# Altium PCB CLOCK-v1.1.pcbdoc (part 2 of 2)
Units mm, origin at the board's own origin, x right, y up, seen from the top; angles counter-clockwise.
Board outline 180 x 92.5 mm, 2 copper layers (Top Layer, Bottom Layer); 120 components, 111 nets, 414 pads, 6 vias.
Unrouted connection lines stored in the file: 2.
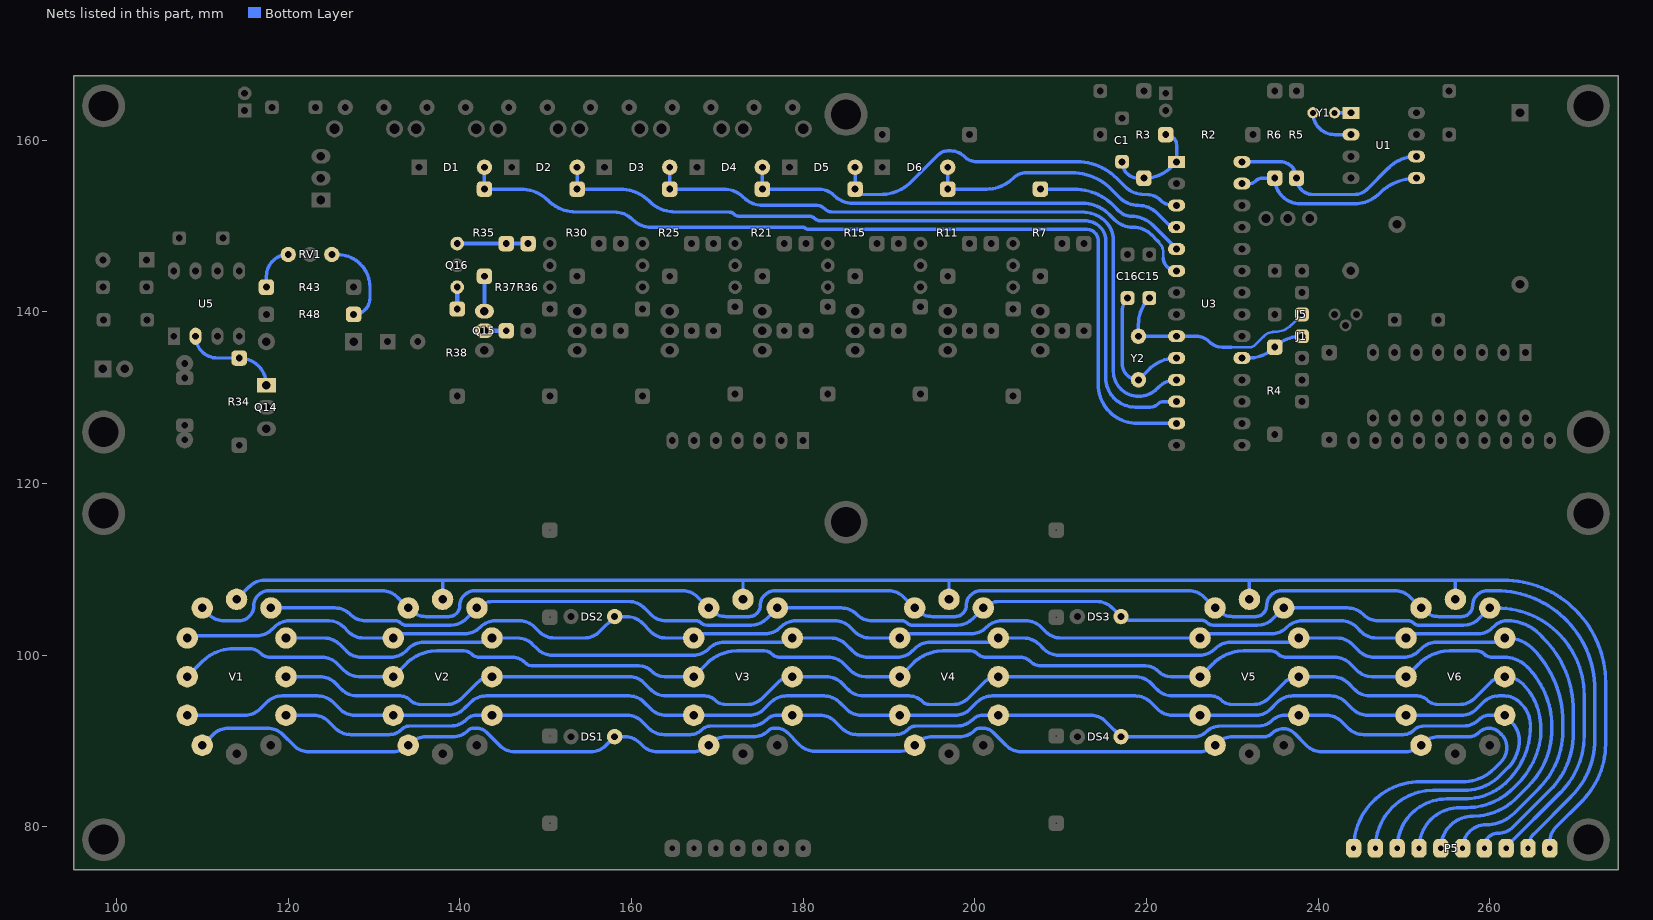
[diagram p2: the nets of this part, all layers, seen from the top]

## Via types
v1: diameter 1.6, hole 0.8, Top Layer to Bottom Layer, 6 vias

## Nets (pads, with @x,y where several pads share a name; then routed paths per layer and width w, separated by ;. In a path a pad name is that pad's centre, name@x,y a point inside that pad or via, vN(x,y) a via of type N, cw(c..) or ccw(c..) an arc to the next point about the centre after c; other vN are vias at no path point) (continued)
NetQ14_1: Q14.1 R34.2 U5.2 | length 15.5
  Bottom Layer w0.4: Q14.1@117.475,131.445 ccw(c114.3,131.445) R34.2@114.3,134.62 111.76,134.62 ; 111.76,134.62 cw(c111.76,137.16) U5.2@109.22,137.16 ccw(c111.76,137.16) 111.76,134.62
NetQ15_2: Q15.2 R37.1 | length 2.5
  Bottom Layer w0.5: Q15.2@142.875,137.795 R37.1@145.415,137.795
NetQ15_3: Q15.3 R35.2 | length 4.1
  Bottom Layer w0.5: Q15.3@142.875,140.081 R35.2@142.875,144.145
NetQ16_1: Q16.1 R38.2 | length 2.5
  Bottom Layer w0.5: R38.2@139.7,140.335 Q16.1@139.7,142.875
NetQ16_3: Q16.3 R36.1 R37.2 | length 8.3
  Bottom Layer w0.5: Q16.3@139.7,147.955 R37.2@145.415,147.955 R36.1@147.955,147.955
NetR43_1: R43.1 RV1.1 | length 5.3
  Bottom Layer w0.4: R43.1@117.475,142.875 117.475,144.145 cw(c120.015,144.145) RV1.1@120.015,146.685
NetR48_1: R48.1 RV1.3 | length 10.9
  Bottom Layer w0.4: RV1.3@125.095,146.685 125.73,146.685 cw(c125.73,142.875) 129.54,142.875 129.54,141.605 cw(c127.635,141.605) R48.1@127.635,139.7
NetU1_1: U1.1 Y1.1 | length 1.9
  Bottom Layer w0.4: Y1.1@241.935,163.195 U1.1@243.84,163.195
NetU1_2: U1.2 Y1.2 | length 5.9
  Bottom Layer w0.4: Y1.2@239.395,163.195 ccw(c241.935,163.195) 241.935,160.655 U1.2@243.84,160.655
RESET: C1.2 R2.2 R3.2 U3.1 | length 11.9
  Bottom Layer w0.4: C1.2@217.17,157.48 ccw(c219.075,157.48) 219.075,155.575 R3.2@219.71,155.575 ccw(c219.71,160.174) 222.962,156.922 U3.1@223.52,157.48 223.52,159.385 ccw(c222.25,159.385) R2.2@222.25,160.655
SCK: J1.1 R4.1 U3.19 | length 7.7
  Bottom Layer w0.4: U3.19@231.14,134.62 231.884,134.62 ccw(c231.884,138.956) R4.1@234.95,135.89 cw(c238.016,132.824) 238.016,137.16 J1.1@238.125,137.16
SCL: R5.1 U1.6 U3.28 | length 24
  Bottom Layer w0.4: U3.28@231.14,157.48 235.585,157.48 cw(c235.585,155.575) R5.1@237.49,155.575 ccw(c239.395,155.575) 239.395,153.67 244.212,153.67 ccw(c244.212,155.838) 245.745,154.305 248.208,156.768 cw(c251.46,153.516) U1.6@251.46,158.115
SDA: R6.1 U1.5 U3.27 | length 23
  Bottom Layer w0.4: U3.27@231.14,154.94 231.961,154.94 ccw(c231.961,156.024) 232.727,155.258 cw(c233.494,154.491) 233.494,155.575 R6.1@234.95,155.575 ccw(c237.934,155.575) 237.934,152.59 244.255,152.59 ccw(c244.255,156.648) 247.124,153.779 cw(c251.46,149.443) U1.5@251.46,155.575
X1: R7.1 U3.5 | length 18.3
  Bottom Layer w0.4: R7.1@207.645,154.305 211.555,154.305 cw(c211.555,147.801) 216.154,152.4 216.81,151.744 ccw(c218.293,153.227) 218.293,151.13 cw(c218.293,147.708) 220.712,150.128 U3.5@223.52,147.32
X2: D6.1 R11.1 U3.4 | length 32.4
  Bottom Layer w0.4: R11.1@196.85,153.67 R11.1@196.85,154.305 ; D6.1@196.85,156.845 R11.1@196.85,154.305 ; U3.4@223.52,149.86 cw(c223.52,151.393) 222.436,150.309 221.243,151.502 ccw(c219.075,149.334) 219.075,152.4 cw(c219.075,155.466) 216.907,153.298 215.9,154.305 ccw(c211.301,149.706) 211.301,156.21 206.003,156.21 ccw(c206.003,154.042) 204.47,155.575 cw(c201.404,158.641) 201.404,154.305 R11.1@196.85,154.305
X3: D5.1 R15.1 U3.3 | length 44.6
  Bottom Layer w0.4: R15.1@186.055,153.67 R15.1@186.055,154.305 ; D5.1@186.055,156.845 R15.1@186.055,154.305 ; U3.3@223.52,152.4 223.148,152.4 cw(c223.148,154.568) 221.615,153.035 ccw(c220.082,151.502) 220.082,153.67 219.71,153.67 cw(c219.71,156.736) 217.542,154.568 216.535,155.575 ccw(c211.936,150.976) 211.936,157.48 200.288,157.48 cw(c200.288,159.648) 198.755,158.115 ccw(c197.222,156.582) 197.222,158.75 196.85,158.75 ccw(c196.85,157.217) 195.766,158.301 192.662,155.197 cw(c188.976,158.882) 188.976,153.67 186.69,153.67 R15.1@186.055,154.305
X4: D4.1 R21.1 U3.6 | length 56.9
  Bottom Layer w0.3: 220.84,148.73 221.226,148.344 cw(c219.43,146.548) 221.228,148.342 cw(c219.43,146.548) 221.234,148.336 cw(c219.43,146.548) 221.566,147.923 cw(c220.589,146.947) 221.766,147.668 ; 221.97,146.271 221.97,146.548 221.97,146.947 ; 221.97,146.812 221.97,146.947 ; 221.766,147.668 cw(c220.589,146.947) 221.871,147.459 ; 221.766,147.668 cw(c220.589,146.947) 221.871,147.459 ; 221.871,147.459 cw(c220.589,146.947) 221.97,146.947 ; 221.871,147.459 cw(c220.589,146.947) 221.97,146.947
  Bottom Layer w0.4: D4.1@175.26,156.845 R21.1@175.26,154.305 181.802,154.305 cw(c181.802,151.703) 183.642,153.543 ccw(c185.788,155.689) 185.788,152.654 212.58,152.654 cw(c212.58,148.318) 215.646,151.384 216.272,150.758 ccw(c218.44,152.926) 218.44,149.86 cw(c218.44,146.794) 220.607,148.963 221.228,148.342 221.414,148.156 221.234,148.336 ; 221.97,146.271 ccw(c223.36,146.271) 222.377,145.288 222.436,145.229 ccw(c223.52,146.313) U3.6@223.52,144.78
X5: D3.1 R25.1 U3.11 | length 81.6
  Bottom Layer w0.4: D3.1@164.465,156.845 R25.1@164.465,154.305 170.738,154.305 cw(c170.738,151.053) 173.038,153.353 ccw(c175.337,155.652) 175.337,152.4 181.579,152.4 cw(c181.579,151.099) 182.499,152.019 ccw(c183.419,152.939) 183.419,151.638 212.506,151.638 cw(c212.506,147.736) 215.265,150.495 cw(c213.119,148.349) 216.154,148.349 216.154,133.096 ccw(c219.091,133.096) 219.091,130.159 ccw(c219.091,133.186) 221.232,131.046 221.379,131.193 cw(c223.52,129.053) U3.11@223.52,132.08
X6: D2.1 R30.1 U3.12 | length 92.8
  Bottom Layer w0.4: D2.1@153.67,156.845 R30.1@153.67,154.305 158.679,154.305 cw(c158.679,149.535) 162.052,152.908 ccw(c165.118,155.974) 165.118,151.638 171.345,151.638 cw(c171.345,150.771) 171.958,151.384 ccw(c172.571,151.997) 172.571,151.13 180.743,151.13 cw(c180.743,150.263) 181.356,150.876 ccw(c181.969,151.489) 181.969,150.622 212.79,150.622 cw(c212.79,148.02) 214.63,149.86 cw(c213.097,148.327) 215.265,148.327 215.265,132.334 ccw(c218.694,132.334) 218.694,128.905 220.441,128.905 ccw(c220.441,130.206) 221.361,129.286 cw(c221.974,128.673) 221.974,129.54 U3.12@223.52,129.54
X7: D1.1 R35.1 U3.13 | length 104.8
  Bottom Layer w0.4: D1.1@142.875,156.845 R35.1@142.875,154.305 147.085,154.305 cw(c147.085,149.752) 150.305,152.972 ccw(c153.524,156.191) 153.524,151.638 158.001,151.638 cw(c158.001,148.603) 160.147,150.749 ccw(c162.293,152.895) 162.293,149.86 180.086,149.86 ccw(c180.699,150.473) 180.123,149.825 ; U3.13@223.52,127 218.948,127 cw(c218.948,131.572) 214.376,131.572 214.376,148.305 ccw(c213.074,148.305) 213.995,149.225 ccw(c213.075,148.305) 213.075,149.606 180.699,149.606 cw(c180.699,150.473) 180.367,149.672 ; 180.123,149.825 ccw(c180.699,150.473) 180.367,149.672 ; 180.123,149.825 cw(c179.914,149.218) 180.367,149.672
XTAL1: C15.1 J5.1 U3.9 Y2.2 | length 25.5
  Bottom Layer w0.3: 229.87,135.89 232.051,135.89 ccw(c232.051,136.757) 232.664,136.144 233.649,137.129 cw(c234.95,135.828) 234.95,137.668 ccw(c234.95,140.427) 236.901,138.476 J5.1@238.125,139.7
  Bottom Layer w0.4: C15.1@220.345,141.605 ccw(c223.411,138.539) 219.075,138.539 Y2.2@219.075,137.16 U3.9@223.52,137.16 225.797,137.16 cw(c225.797,134.992) 227.33,136.525 ccw(c228.863,138.058) 228.863,135.89 229.87,135.89
XTAL2: C16.1 U3.10 Y2.1 | length 16.1
  Bottom Layer w0.4: C16.1@217.805,141.605 ccw(c219.338,140.072) 217.17,140.072 217.17,133.985 ccw(c219.075,133.985) Y2.1@219.075,132.08 220.268,133.273 cw(c223.52,130.021) U3.10@223.52,134.62
Y1: DS1.1 P5.10 V1.11 V2.11 V3.11 V4.11 V5.11 V6.11 | length 188.6
  Bottom Layer w0.4: V1.11@109.999,89.498 111.257,90.756 cw(c113.053,88.96) 113.053,91.5 117.582,91.5 cw(c117.582,88.96) 119.378,90.756 120.64,89.494 ccw(c122.436,91.29) 122.436,88.75 132.199,88.75 ccw(c132.199,91.29) 133.995,89.494 V2.11@133.999,89.498 134.257,89.756 cw(c136.053,87.96) 136.053,90.5 139.198,90.5 ccw(c139.198,93.04) 140.994,91.244 141,91.25 cw(c141.604,90.646) 141.604,91.5 142,91.5 cw(c142,89.969) 143.082,91.052 144.66,89.474 ccw(c146.456,91.27) 146.456,88.73 155.218,88.73 ccw(c155.218,91.27) 157.014,89.474 DS1.1@158.04,90.5 159.25,90.5 cw(c159.25,88.086) 160.957,89.793 161.256,89.494 ccw(c163.052,91.29) 163.052,88.75 167.199,88.75 ccw(c167.199,91.29) 168.995,89.494 V3.11@168.999,89.498 169.257,89.756 cw(c171.053,87.96) 171.053,90.5 174.198,90.5 ccw(c174.198,93.04) 175.994,91.244 176,91.25 cw(c176.604,90.646) 176.604,91.5 176.927,91.5 cw(c176.927,89.793) 178.134,91 179.573,89.561 ccw(c181.369,91.357) 181.369,88.817 191.354,88.817 ccw(c191.354,91.143) V4.11@192.999,89.498 193.257,89.756 cw(c195.053,87.96) 195.053,90.5 198.198,90.5 ccw(c198.198,93.04) 199.994,91.244 200,91.25 ; P5.10@244.14,77.5 cw(c251.89,77.5) 251.89,85.25 256.853,85.25 ccw(c256.853,90.434) 260.518,86.768 261.293,87.543 ccw(c259.586,89.25) 262,89.25 ccw(c259.866,89.25) 261.375,90.759 261.123,91.011 ccw(c259.942,89.829) 259.942,91.5 ccw(c259.942,89.829) 258.761,91.011 258.75,91 258.761,91.011 ; 258.749,90.999 cw(c257.543,92.207) 257.543,90.5 254.053,90.5 ccw(c254.053,87.96) 252.257,89.756 V6.11@251.999,89.498 251.995,89.494 cw(c250.199,91.29) 250.199,88.75 240.436,88.75 cw(c240.436,91.29) 238.64,89.494 237.259,90.875 ccw(c235.75,89.366) 236.237,91.444 235.998,91.444 ccw(c235.998,89.502) 234.625,90.875 cw(c233.72,91.78) 233.72,90.5 230.053,90.5 ccw(c230.053,87.96) 228.257,89.756 V5.11@227.999,89.498 227.995,89.494 cw(c226.199,91.29) 226.199,88.75 205.436,88.75 cw(c205.436,91.29) 203.64,89.494 202.067,91.067 ccw(c201.022,90.022) 201.022,91.5 200.604,91.5 ; 200,91.25 cw(c200.604,90.646) 200.604,91.5 ; 200,91.25 cw(c200.604,90.646) 200.604,91.5
Y2: P5.8 V1.10 V2.10 V3.10 V4.10 V5.10 V6.10 | length 190.3
  Bottom Layer w0.4: V1.10@108.249,92.999 114.947,92.999 ccw(c114.947,95.539) 116.743,93.743 117.506,94.506 cw(c119.302,92.71) 119.302,95.25 123.447,95.25 cw(c123.447,92.71) 125.243,94.506 126.006,93.743 ccw(c127.802,95.539) 127.802,92.999 V2.10@132.249,92.999 138.698,92.999 ccw(c138.698,95.539) 140.494,93.743 141.257,94.506 cw(c143.053,92.71) 143.053,95.25 159.75,95.25 cw(c159.75,92.838) 161.456,94.544 162.256,93.743 ccw(c164.052,95.539) 164.052,92.999 V3.10@167.249,92.999 173.697,92.999 ccw(c173.697,95.539) 175.493,93.743 176.256,94.506 cw(c178.052,92.71) 178.052,95.25 182.447,95.25 cw(c182.447,92.71) 184.243,94.506 185.006,93.743 ccw(c186.802,95.539) 186.802,92.999 V4.10@191.249,92.999 197.698,92.999 ccw(c197.698,95.539) 199.494,93.743 200.257,94.506 cw(c202.053,92.71) 202.053,95.25 218.697,95.25 cw(c218.697,92.71) 220.493,94.506 221.256,93.743 ccw(c223.052,95.539) 223.052,92.999 V5.10@226.249,92.999 232.75,92.999 ccw(c232.75,95.411) 234.456,93.706 235.256,94.506 cw(c237.052,92.71) 237.052,95.25 241.447,95.25 cw(c241.447,92.71) 243.243,94.506 244.006,93.743 ccw(c245.802,95.539) 245.802,92.999 V6.10@250.249,92.999 256.697,92.999 ccw(c256.697,95.539) 258.493,93.743 259.256,94.506 cw(c261.052,92.71) 261.052,95.25 261.698,95.25 cw(c261.698,92.71) 263.494,94.506 263.689,94.311 cw(c261.129,91.75) 264.75,91.75 cw(c255.697,91.75) 262.098,85.348 cw(c257.032,90.414) 257.032,83.25 254.97,83.25 ccw(c254.97,77.5) P5.8@249.22,77.5
Y3: P5.6 V1.9 V2.9 V3.9 V4.9 V5.9 V6.9 | length 196.1
  Bottom Layer w0.4: V1.9@108.249,97.5 110.011,99.262 cw(c113.603,95.67) 113.603,100.75 115.543,100.75 cw(c115.543,99.043) 116.75,100.25 ccw(c117.957,101.457) 117.957,99.75 123.948,99.75 cw(c123.948,97.21) 125.744,99.006 126.506,98.244 ccw(c128.302,100.04) 128.302,97.5 V2.9@132.249,97.5 133.761,99.012 cw(c137.353,95.42) 137.353,100.5 140.47,100.5 cw(c140.47,99.22) 141.375,100.125 ccw(c142.28,101.03) 142.28,99.75 146.116,99.75 cw(c146.116,97.616) 147.625,99.125 ccw(c148.53,100.03) 148.53,98.75 160.866,98.75 cw(c160.866,96.616) 162.375,98.125 ccw(c163.884,99.634) 163.884,97.5 V3.9@167.249,97.5 168.761,99.012 cw(c172.353,95.42) 172.353,100.5 175.47,100.5 cw(c175.47,99.22) 176.375,100.125 ccw(c177.28,101.03) 177.28,99.75 182.948,99.75 cw(c182.948,97.21) 184.744,99.006 185.506,98.244 ccw(c187.302,100.04) 187.302,97.5 V4.9@191.249,97.5 192.761,99.012 cw(c196.353,95.42) 196.353,100.5 199.47,100.5 cw(c199.47,99.22) 200.375,100.125 ccw(c201.28,101.03) 201.28,99.75 205.293,99.75 cw(c205.293,98.043) 206.5,99.25 ccw(c207.707,100.457) 207.707,98.75 219.866,98.75 cw(c219.866,96.616) 221.375,98.125 ccw(c222.884,99.634) 222.884,97.5 V5.9@226.249,97.5 227.761,99.012 cw(c231.353,95.42) 231.353,100.5 234.47,100.5 cw(c234.47,99.22) 235.375,100.125 ccw(c236.28,101.03) 236.28,99.75 241.948,99.75 cw(c241.948,97.21) 243.744,99.006 244.506,98.244 ccw(c246.302,100.04) 246.302,97.5 V6.9@250.249,97.5 251.761,99.012 cw(c255.353,95.42) 255.353,100.5 258.47,100.5 cw(c258.47,99.22) 259.375,100.125 ccw(c260.28,101.03) 260.28,99.75 261.698,99.75 cw(c261.698,96.003) 264.348,98.652 cw(c257.34,91.645) 267.25,91.645 267.25,91.393 cw(c257.852,91.393) 264.497,84.747 263.086,83.336 cw(c258.05,88.372) 258.05,81.25 ccw(c258.05,77.5) P5.6@254.3,77.5
Y4: DS2.1 P5.4 V1.8 V2.8 V3.8 V4.8 V5.8 V6.8 | length 196.8
  Bottom Layer w0.4: V1.8@108.249,102.001 108.498,102.25 116.313,102.25 ccw(c116.313,104.79) 118.109,102.994 118.372,103.256 cw(c120.168,101.46) 120.168,104 124.75,104 cw(c124.75,101.584) 126.459,103.292 127.006,102.745 ccw(c128.802,104.541) 128.802,102.001 V2.8@132.249,102.001 cw(c133.454,100.796) 133.454,102.5 140.563,102.5 ccw(c140.563,105.04) 142.359,103.244 142.372,103.256 cw(c144.168,101.46) 144.168,104 146.948,104 cw(c146.948,101.46) 148.744,103.256 149.256,102.744 ccw(c151.052,104.54) 151.052,102 154.5,102 ccw(c154.5,104.511) 156.275,102.735 DS2.1@158.04,104.5 159.448,104.5 cw(c159.448,101.96) 161.244,103.756 162.255,102.745 ccw(c164.051,104.541) 164.051,102.001 V3.8@167.249,102.001 cw(c168.454,100.796) 168.454,102.5 175.563,102.5 ccw(c175.563,105.04) 177.359,103.244 177.372,103.256 cw(c179.168,101.46) 179.168,104 183.699,104 cw(c183.699,101.46) 185.495,103.256 186.006,102.745 ccw(c187.802,104.541) 187.802,102.001 V4.8@191.249,102.001 cw(c192.454,100.796) 192.454,102.5 199.563,102.5 ccw(c199.563,105.04) 201.359,103.244 201.372,103.256 cw(c203.168,101.46) 203.168,104 205.948,104 cw(c205.948,101.46) 207.744,103.256 208.255,102.745 ccw(c210.051,104.541) 210.051,102.001 V5.8@226.249,102.001 cw(c227.454,100.796) 227.454,102.5 234.563,102.5 ccw(c234.563,105.04) 236.359,103.244 236.372,103.256 cw(c238.168,101.46) 238.168,104 242.699,104 cw(c242.699,101.46) 244.495,103.256 245.006,102.745 ccw(c246.802,104.541) 246.802,102.001 V6.8@250.249,102.001 cw(c251.454,100.796) 251.454,102.5 258.668,102.5 ccw(c258.668,104.832) 260.317,103.183 260.522,103.388 cw(c262,101.909) 262,104 262.129,104 cw(c262.129,98.879) 265.75,102.5 266.253,101.997 cw(c257.812,93.555) 269.75,93.555 269.75,90.893 cw(c260.352,90.893) 266.997,84.247 262.744,79.994 cw(c260.948,81.79) 260.948,79.25 ccw(c260.948,77.682) 259.38,77.682 P5.4@259.38,77.5
Y5: P5.2 V1.7 V2.7 V3.7 V4.7 V5.7 V6.7 | length 206.2
  Bottom Layer w0.4: V1.7@109.999,105.502 110.757,104.744 ccw(c112.553,106.54) 112.553,104 114.25,104 ccw(c114.25,105.75) 116,105.75 cw(c117.75,105.75) 117.75,107.5 130.949,107.5 cw(c130.949,104.96) 132.745,106.756 V2.7@133.999,105.502 134.257,105.244 ccw(c136.053,107.04) 136.053,104.5 138.72,104.5 ccw(c138.72,105.78) 139.625,104.875 139.646,104.896 ccw(c138.793,105.75) 140,105.75 cw(c141.75,105.75) 141.75,107.5 165.949,107.5 cw(c165.949,104.96) 167.745,106.756 V3.7@168.999,105.502 169.256,105.244 ccw(c171.053,107.04) 171.053,104.5 173.721,104.5 ccw(c173.721,105.779) 174.625,104.875 174.646,104.896 ccw(c173.793,105.75) 175,105.75 cw(c176.75,105.75) 176.75,107.5 189.949,107.5 cw(c189.949,104.96) 191.745,106.756 V4.7@192.999,105.502 193.257,105.244 ccw(c195.053,107.04) 195.053,104.5 197.72,104.5 ccw(c197.72,105.78) 198.625,104.875 198.647,104.897 ccw(c197.793,105.75) 199,105.75 cw(c200.75,105.75) 200.75,107.5 224.949,107.5 cw(c224.949,104.96) 226.745,106.756 V5.7@227.999,105.502 228.257,105.244 ccw(c230.053,107.04) 230.053,104.5 232.72,104.5 ccw(c232.72,105.78) 233.625,104.875 233.647,104.897 ccw(c232.793,105.75) 234,105.75 cw(c235.75,105.75) 235.75,107.5 248.949,107.5 cw(c248.949,104.96) 250.745,106.756 V6.7@251.999,105.502 252.257,105.244 ccw(c254.053,107.04) 254.053,104.5 256.72,104.5 ccw(c256.72,105.78) 257.625,104.875 257.646,104.896 ccw(c256.793,105.75) 258,105.75 cw(c259.75,105.75) 259.75,107.5 260.75,107.5 cw(c260.75,96) 272.25,96 272.25,90.183 cw(c262.852,90.183) 269.497,83.537 265.167,79.207 ccw(c266.874,77.5) P5.2@264.46,77.5
Y6: P5.1 V1.6 V2.6 V3.6 V4.6 V5.6 V6.6 | length 199.9
  Bottom Layer w0.4: V1.6@114,106.502 115.504,108.006 cw(c117.3,106.21) 117.3,108.75 138,108.75 ; V2.6@138,106.502 138,108.75 ; V3.6@173,106.502 173,108.75 ; V4.6@197,106.502 197,108.75 ; V5.6@232,106.502 232,108.75 ; V6.6@256,106.502 256,108.75 ; P5.1@267,77.5 267,78.198 cw(c269.54,78.198) 267.744,79.994 270.747,82.997 ccw(c264.102,89.643) 273.5,89.643 273.5,96.812 ccw(c261.562,96.812) 261.562,108.75 256,108.75 ; 138,108.75 173,108.75 ; 173,108.75 197,108.75 ; 197,108.75 232,108.75 ; 232,108.75 256,108.75
Y7: DS3.1 P5.3 V1.5 V2.5 V3.5 V4.5 V5.5 V6.5 | length 187.3
  Bottom Layer w0.4: V1.5@118.001,105.502 125.446,105.502 cw(c125.446,102.962) 127.242,104.758 127.256,104.744 ccw(c129.052,106.54) 129.052,104 132.512,104 cw(c132.512,103.146) 133.116,103.75 ccw(c133.72,104.354) 133.72,103.5 138.947,103.5 ccw(c138.947,106.04) 140.743,104.244 V2.5@142.001,105.502 cw(c143.808,103.695) 143.808,106.25 159.698,106.25 cw(c159.698,103.71) 161.494,105.506 162.256,104.744 ccw(c164.052,106.54) 164.052,104 167.594,104 cw(c167.594,103.344) 168.058,103.808 ccw(c168.802,104.552) 168.802,103.5 173.947,103.5 ccw(c173.947,106.04) 175.743,104.244 V3.5@177.001,105.502 184.448,105.502 cw(c184.448,102.962) 186.244,104.758 186.258,104.744 ccw(c188.054,106.54) 188.054,104 191.512,104 cw(c191.512,103.146) 192.116,103.75 ccw(c192.72,104.354) 192.72,103.5 197.947,103.5 ccw(c197.947,106.04) 199.743,104.244 V4.5@201.001,105.502 201.005,105.506 cw(c202.801,103.71) 202.801,106.25 214.238,106.25 cw(c214.238,103.71) 216.034,105.506 DS3.1@217.04,104.5 ccw(c218.107,105.567) 218.107,104.058 226.413,104.058 cw(c226.413,103.105) 227.087,103.779 ccw(c227.761,104.453) 227.761,103.5 232.947,103.5 ccw(c232.947,106.04) 234.743,104.244 V5.5@236.001,105.502 243.446,105.502 cw(c243.446,102.962) 245.242,104.758 245.256,104.744 ccw(c247.052,106.54) 247.052,104 250.512,104 cw(c250.512,103.146) 251.116,103.75 ccw(c251.72,104.354) 251.72,103.5 256.947,103.5 ccw(c256.947,106.04) 258.743,104.244 V6.5@260.001,105.502 260.84,105.502 cw(c260.84,95.342) 271,95.342 271,90.643 cw(c261.602,90.643) 268.247,83.997 262.04,77.79 ccw(c262.33,77.5) P5.3@261.92,77.5
Y8: P5.5 V1.4 V2.4 V3.4 V4.4 V5.4 V6.4 | length 182
  Bottom Layer w0.4: V1.4@119.751,102.001 124.197,102.001 cw(c124.197,99.461) 125.993,101.257 126.756,100.494 ccw(c128.552,102.29) 128.552,99.75 131.948,99.75 ccw(c131.948,102.29) 133.744,100.494 134.006,100.756 cw(c135.802,98.96) 135.802,101.5 142.542,101.5 ccw(c142.542,103.21) V2.4@143.751,102.001 146.75,102.001 cw(c146.75,99.589) 148.456,101.294 149.006,100.744 ccw(c150.802,102.54) 150.802,100 167.198,100 ccw(c167.198,102.54) 168.994,100.744 169.006,100.756 cw(c170.802,98.96) 170.802,101.5 177.542,101.5 ccw(c177.542,103.21) V3.4@178.751,102.001 183.197,102.001 cw(c183.197,99.461) 184.993,101.257 185.756,100.494 ccw(c187.552,102.29) 187.552,99.75 190.948,99.75 ccw(c190.948,102.29) 192.744,100.494 193.006,100.756 cw(c194.802,98.96) 194.802,101.5 201.542,101.5 ccw(c201.542,103.21) V4.4@202.751,102.001 205.698,102.001 cw(c205.698,99.461) 207.494,101.257 208.007,100.744 ccw(c209.803,102.54) 209.803,100 226.198,100 ccw(c226.198,102.54) 227.994,100.744 228.006,100.756 cw(c229.802,98.96) 229.802,101.5 236.542,101.5 ccw(c236.542,103.21) V5.4@237.751,102.001 242.197,102.001 cw(c242.197,99.461) 243.993,101.257 244.756,100.494 ccw(c246.552,102.29) 246.552,99.75 249.948,99.75 ccw(c249.948,102.29) 251.744,100.494 252.006,100.756 cw(c253.802,98.96) 253.802,101.5 261.25,101.5 V6.4@261.751,102.001 261.98,102.001 cw(c261.98,97.73) 265,100.75 265.003,100.747 cw(c256.562,92.305) 268.5,92.305 268.5,91.143 cw(c259.102,91.143) 265.747,84.497 262.851,81.601 cw(c259.59,84.861) 259.59,80.25 ccw(c259.59,77.5) P5.5@256.84,77.5
Y9: P5.7 V1.3 V2.3 V3.3 V4.3 V5.3 V6.3 | length 188.6
  Bottom Layer w0.4: V1.3@119.751,97.5 123.698,97.5 cw(c123.698,94.96) 125.494,96.756 126.256,95.994 ccw(c128.052,97.79) 128.052,95.25 133.043,95.25 cw(c133.043,93.543) 134.25,94.75 ccw(c135.457,95.957) 135.457,94.25 138.448,94.25 ccw(c138.448,96.79) 140.244,94.994 142.042,96.792 cw(c143.751,95.083) V2.3@143.751,97.5 159.75,97.5 cw(c159.75,95.086) 161.457,96.793 162.256,95.994 ccw(c164.052,97.79) 164.052,95.25 168.543,95.25 cw(c168.543,93.543) 169.75,94.75 ccw(c170.957,95.957) 170.957,94.25 173.448,94.25 ccw(c173.448,96.79) 175.244,94.994 177.043,96.793 cw(c178.751,95.083) V3.3@178.751,97.5 182.698,97.5 cw(c182.698,94.96) 184.494,96.756 185.256,95.994 ccw(c187.052,97.79) 187.052,95.25 192.366,95.25 cw(c192.366,93.116) 193.875,94.625 ccw(c194.78,95.53) 194.78,94.25 197.448,94.25 ccw(c197.448,96.79) 199.244,94.994 201.043,96.793 cw(c202.751,95.083) V4.3@202.751,97.5 218.698,97.5 cw(c218.698,94.96) 220.494,96.756 221.256,95.994 ccw(c223.052,97.79) 223.052,95.25 227.543,95.25 cw(c227.543,93.543) 228.75,94.75 ccw(c229.957,95.957) 229.957,94.25 232.448,94.25 ccw(c232.448,96.79) 234.244,94.994 236.042,96.792 cw(c237.751,95.083) V5.3@237.751,97.5 241.698,97.5 cw(c241.698,94.96) 243.494,96.756 244.256,95.994 ccw(c246.052,97.79) 246.052,95.25 251.543,95.25 cw(c251.543,93.543) 252.75,94.75 ccw(c253.957,95.957) 253.957,94.25 256.448,94.25 ccw(c256.448,96.79) 258.244,94.994 260.042,96.792 cw(c261.751,95.083) V6.3@261.751,97.5 261.8,97.5 cw(c261.8,94.604) 263.848,96.652 cw(c258.819,91.623) 265.924,91.946 ; 175.75,95.5 177.042,96.792 ; 199.75,95.5 201.042,96.792 ; P5.7@251.76,77.5 cw(c256.505,77.5) 256.505,82.245 257.306,82.245 ccw(c257.306,89.944) 262.75,84.5 263.247,84.997 ccw(c256.602,91.643) 265.931,90.508 ; 265.924,91.946 cw(c258.819,91.623) 265.931,91.623 265.931,90.508 ; 265.924,91.946 cw(c259.273,91.273) 265.958,91.273 ; 265.924,91.946 cw(c259.273,91.273) 265.958,91.273 ; 265.931,90.508 ccw(c256.602,91.643) 265.958,90.754 265.958,91.273
Y10: DS4.1 P5.9 V1.2 V2.2 V3.2 V4.2 V5.2 V6.2 | length 176
  Bottom Layer w0.4: V1.2@119.751,92.999 122.949,92.999 cw(c122.949,90.459) 124.745,92.255 125.506,91.494 ccw(c127.302,93.29) 127.302,90.75 131.764,90.75 ccw(c131.764,92.851) 133.25,91.365 cw(c134.178,90.437) 134.178,91.75 138.948,91.75 ccw(c138.948,94.29) 140.744,92.494 140.75,92.5 cw(c141.956,91.294) 141.956,92.999 V2.2@143.751,92.999 159.5,92.999 cw(c159.5,90.583) 161.209,92.291 162.006,91.494 ccw(c163.802,93.29) 163.802,90.75 166.846,90.75 ccw(c166.846,92.654) 168.192,91.308 cw(c169.26,90.24) 169.26,91.75 173.949,91.75 ccw(c173.949,94.29) 175.745,92.494 175.75,92.5 cw(c176.956,91.294) 176.956,92.999 V3.2@178.751,92.999 181.949,92.999 cw(c181.949,90.459) 183.745,92.255 184.506,91.494 ccw(c186.302,93.29) 186.302,90.75 190.764,90.75 ccw(c190.764,92.851) 192.25,91.365 cw(c193.178,90.437) 193.178,91.75 197.948,91.75 ccw(c197.948,94.29) 199.744,92.494 199.75,92.5 cw(c200.956,91.294) 200.956,92.999 V4.2@202.751,92.999 213.489,92.999 cw(c213.489,90.459) 215.285,92.255 DS4.1@217.04,90.5 225.596,90.5 ccw(c225.596,92.404) 226.942,91.058 cw(c228.614,89.387) 228.614,91.75 233.117,91.75 ccw(c233.117,93.882) 234.625,92.375 cw(c236.132,90.867) 236.132,92.999 V5.2@237.751,92.999 240.949,92.999 cw(c240.949,90.459) 242.745,92.255 243.506,91.494 ccw(c245.302,93.29) 245.302,90.75 249.927,90.75 ccw(c249.927,92.457) 251.135,91.25 cw(c252.342,90.043) 252.342,91.75 256.948,91.75 ccw(c256.948,94.29) 258.744,92.494 258.75,92.5 cw(c259.955,91.295) 259.955,92.999 V6.2@261.751,92.999 262.558,92.192 cw(c260.425,90.058) 263.442,90.058 cw(c258.936,90.058) 262.122,86.872 261.25,86 cw(c257.025,90.225) 257.025,84.25 253.43,84.25 ccw(c253.43,77.5) P5.9@246.68,77.5
pads on no net: U1.7 U3.14 V1.12 V2.12 V3.12 V4.12 V5.12 V6.12
copper on no net: | length 106.8
  Bottom Layer w0.2: 114.1,97.5 ccw(c114,97.5) 114.1,97.5 ; 116,97.5 ccw(c114,97.5) 116,97.5 ; 138.1,97.5 ccw(c138,97.5) 138.1,97.5 ; 140,97.5 ccw(c138,97.5) 140,97.5 ; 155.6,90.5 ccw(c155.5,90.5) 155.6,90.5 ; 155.6,104.5 ccw(c155.5,104.5) 155.6,104.5 ; 156.5,90.5 ccw(c155.5,90.5) 156.5,90.5 ; 156.5,104.5 ccw(c155.5,104.5) 156.5,104.5 ; 173.1,97.5 ccw(c173,97.5) 173.1,97.5 ; 175,97.5 ccw(c173,97.5) 175,97.5 ; 197.1,97.5 ccw(c197,97.5) 197.1,97.5 ; 199,97.5 ccw(c197,97.5) 199,97.5 ; 214.6,90.5 ccw(c214.5,90.5) 214.6,90.5 ; 214.6,104.5 ccw(c214.5,104.5) 214.6,104.5 ; 215.5,90.5 ccw(c214.5,90.5) 215.5,90.5 ; 215.5,104.5 ccw(c214.5,104.5) 215.5,104.5 ; 232.1,97.5 ccw(c232,97.5) 232.1,97.5 ; 234,97.5 ccw(c232,97.5) 234,97.5 ; 256.1,97.5 ccw(c256,97.5) 256.1,97.5 ; 258,97.5 ccw(c256,97.5) 258,97.5

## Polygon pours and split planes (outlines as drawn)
GND on Bottom Layer "GND1" (solid, remove dead copper, pour order 3): 95,167.5 95,122.5 275,122.5 275,167.5

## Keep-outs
Keep-Out Layer:
  lines w0.2: 95,120 95,122.5 ; 95,120 95,75 275,75 275,120 ; 95,120 275,120 ; 95,122.5 275,122.5 ; 95,122.5 95,167.5 275,167.5 275,122.5 ; 275,120 275,122.5

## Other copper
Bottom Layer:
  pour cut-out: 139.7,139.7 140.97,139.7 143.51,137.16 213.995,137.16 213.995,136.525 142.875,136.525

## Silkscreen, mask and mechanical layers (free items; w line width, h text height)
Top Overlay:
  circle w0.2: c107.95,129.54 r4
  circle w0.2: c155.5,90.5 r3
  circle w0.2: c155.5,104.5 r3
  circle w0.2: c214.5,104.5 r3
  lines w0.2: 95.965,147.05 105.965,147.05 ; 120.325,123.555 135.475,123.555 135.475,134.255 120.325,134.255 ; 120.975,150.225 105.825,150.225 105.825,160.925 120.975,160.925 ; 225.425,163.195 229.235,163.195 ; 240.03,144.78 241.3,155.575 ; 256.54,139.065 263.525,139.065 ; 95.965,146.05 95.965,161.05 105.965,161.05 105.965,146.05 95.965,146.05 ; 103.45,124.54 103.45,134.54 112.45,134.54 112.45,124.54 103.45,124.54
Title Bot 1:
  lines w0.3: 45,25 45,40 ; 50,25 50,40 ; 125,10 190,10 ; 125,15 190,15 ; 125,20 190,20 ; 125,25 190,25 ; 125,30 190,30 ; 125,45 190,45 ; 125,50 190,50 ; 125,55 190,55
  lines w0.75: 5,20 125,20 ; 5,25 55,25 ; 5,40 55,40 ; 5,45 125,45 ; 5,60 190,60 190,5 ; 23,25 23,45 ; 35,20 35,25 ; 40,25 40,45 ; 55,5 55,45 ; 125,5 125,60 ; 125,35 190,35 ; 125,40 190,40 ; 135,5 135,60 ; 150,5 150,60 ; 173,5 173,60 ; 183,35 183,60 ; 330,292 330,278 400,278 ; 400,30 412,30 ; 400,65 412,65 ; 400,90 412,90 ; 400,115 412,115 ; 400,150 412,150 412,5 400,5 ; 400,172 412,172 412,292 400,292 ; 400,232 412,232 ; 407,5 407,150 ; 407,172 407,292 ; 400,5 400,292 ; 400,5 5,5 5,292 400,292
  text "Перв. примен." at 408.5,252 h3.5 r270
  text "Справ. №" at 408.5,197 h3.5 r270
  text "Подп. и дата" at 408.5,123 h3.5 r270
  text "Инв. № дубл." at 408.5,94 h3.5 r270
  text "Взам. инв. №" at 408.5,68.5 h3.5 r270
  text "Масштаб" at 20,41.5 h3.5
  text "Масса" at 35,41.5 h3.5
  text "Лит." at 50,41.5 h3.5
  text "Подп. и дата" at 408.5,37.5 h3.5 r270
  text "Дата" at 133.5,36.5 h3.5
  text "Подп." at 146,36.5 h3.5
  text "№ докум." at 167.5,36.5 h3.5
  text "Лист" at 181.5,36.5 h3.5
  text "Изм." at 189,36.5 h3.5
  text "*" at 170,31.5 h3.5
  text "Разраб." at 188.5,31.5 h3.5
  text "1:1" at 15,31 h3.5
  text "*" at 32,31 h3.5
  text "*" at 53,31 h3.5
  text "*" at 170,26.5 h3.5
  text "Пров." at 188.5,26.5 h3.5
  text "1" at 14.5,21.5 h3.5
  text "Листов" at 32,21.5 h3.5
  text "1" at 41,21.5 h3.5
  text "Лист" at 52,21.5 h3.5
  text "*" at 170,21.5 h3.5
  text "Т.контр." at 188.5,21.5 h3.5
  text "*" at 170,11.5 h3.5
  text "Н.контр." at 188.5,11.5 h3.5
  text "*" at 31,11 h5
  text "Инв. № подл." at 408.5,9.5 h3.5 r270
  text "*" at 170,6.5 h3.5
  text "Утв." at 188.5,6.5 h3.5
  text "Формат А3" at 50,1.5 h3.5
  text "Копировал" at 110,1.5 h3.5
  text "2.106-A3" at 185,1.5 h3.5
Title Top 2:
  lines w0.3: 230,10 295,10 ; 230,15 295,15
  lines w0.75: 8,30 20,30 ; 8,65 20,65 ; 8,90 20,90 ; 8,115 20,115 ; 13,5 13,150 ; 20,150 8,150 8,5 20,5 ; 20,278 90,278 90,292 ; 218,5 230,5 230,20 415,20 ; 237,5 237,20 ; 247,5 247,20 ; 270,5 270,20 ; 285,5 285,20 ; 295,5 295,20 ; 405,5 405,20 ; 405,13 415,13 ; 20,5 20,292 415,292 415,5 20,5
  text "Подп. и дата" at 11.839,123 h3.5 r90
  text "Инв. № дубл." at 11.839,94 h3.5 r90
  text "Взам. инв. №" at 11.839,68.5 h3.5 r90
  text "Подп. и дата" at 11.839,37.5 h3.5 r90
  text "Лист" at 407,15 h3.5
  text "Инв. № подл." at 11.839,9.5 h3.5 r90
  text "2" at 409,8 h3.5
  text "Изм." at 231.339,6.5 h3.5
  text "Лист" at 238.839,6.5 h3.5
  text "№ докум." at 252.839,6.5 h3.5
  text "Подп." at 274.339,6.5 h3.5
  text "Дата" at 286.839,6.5 h3.5
  text "2.106-A3" at 235.339,1.5 h3.5
  text "Копировал" at 310.339,1.5 h3.5
  text "Формат А3" at 370.339,1.5 h3.5
PCB Bot 1:
  text "АБВГ.123456.001" at 343,287 h7 r180
  text "АБВГ.123456.001" at 402,245 h5 r270
  text "АБВГ.123456.001" at 90.5,50 h7
  text "Плата печатная" at 107,32 h5
PCB Top 2:
  text "АБВГ.123456.001" at 77.339,287 h7 r180
  text "АБВГ.123456.001" at 331,9 h7
PCB Top 1:
  text "АБВГ.123456.001" at 77,287 h7 r180
  text "АБВГ.123456.001" at 18,245 h5 r90
  text "АБВГ.123456.001" at 329.5,50 h7
  text "Плата печатная" at 313,32 h5
PCB Bot 2:
  text "АБВГ.123456.001" at 342.661,287 h7 r180
  text "АБВГ.123456.001" at 89,10 h7
Assy Top 1:
  text "АБВГ.987654.001 СБ" at 81,287 h7 r180
  text "АБВГ.987654.001 СБ" at 326,50 h7
  text "*" at 329,35 h7
  text "Сборочный чертеж" at 311,24 h5
Assy Bot 2:
  text "АБВГ.987654.001 СБ" at 337,287 h7 r180
  text "АБВГ.987654.001 СБ" at 94,10 h7
Assy Bot 1:
  text "АБВГ.987654.001 СБ" at 337,287 h7 r180
  text "АБВГ.987654.001 СБ" at 94,50 h7
  text "*" at 91,35 h7
  text "Сборочный чертеж" at 109,24 h5
Assy Top 2:
  text "АБВГ.987654.001 СБ" at 81,287 h7 r180
  text "АБВГ.987654.001 СБ" at 326,9 h7
Title Top 1:
  lines w0.3: 230,10 295,10 ; 230,15 295,15 ; 230,20 295,20 ; 230,25 295,25 ; 230,30 295,30 ; 230,45 295,45 ; 230,50 295,50 ; 230,55 295,55 ; 370,25 370,40 ; 375,25 375,40
  lines w0.75: 8,30 20,30 ; 8,65 20,65 ; 8,90 20,90 ; 8,115 20,115 ; 8,232 20,232 ; 13,5 13,150 ; 13,172 13,292 ; 20,150 8,150 8,5 20,5 ; 20,172 8,172 8,292 20,292 ; 20,278 90,278 90,292 ; 230,5 230,60 415,60 ; 230,35 295,35 ; 230,40 295,40 ; 237,35 237,60 ; 247,5 247,60 ; 270,5 270,60 ; 285,5 285,60 ; 295,5 295,60 ; 295,20 415,20 ; 295,45 415,45 ; 365,5 365,45 ; 365,25 415,25 ; 365,40 415,40 ; 380,25 380,45 ; 385,20 385,25 ; 397,25 397,45 ; 20,5 415,5 415,292 20,292 ; 20,5 20,292
  text "Перв. примен." at 11.5,252 h3.5 r90
  text "Справ. №" at 11.5,197 h3.5 r90
  text "Подп. и дата" at 11.5,123 h3.5 r90
  text "Инв. № дубл." at 11.5,94 h3.5 r90
  text "Взам. инв. №" at 11.5,68.5 h3.5 r90
  text "Лит." at 370,41.5 h3.5
  text "Масса" at 385,41.5 h3.5
  text "Масштаб" at 400,41.5 h3.5
  text "Подп. и дата" at 11.5,37.5 h3.5 r90
  text "Изм." at 231,36.5 h3.5
  text "Лист" at 238.5,36.5 h3.5
  text "№ докум." at 252.5,36.5 h3.5
  text "Подп." at 274,36.5 h3.5
  text "Дата" at 286.5,36.5 h3.5
  text "Разраб." at 231.5,31.5 h3.5
  text "*" at 250,31.5 h3.5
  text "*" at 367,31 h3.5
  text "*" at 388,31 h3.5
  text "1:1" at 405,31 h3.5
  text "Пров." at 231.5,26.5 h3.5
  text "*" at 250,26.5 h3.5
  text "Т.контр." at 231.5,21.5 h3.5
  text "*" at 250,21.5 h3.5
  text "Лист" at 368,21.5 h3.5
  text "1" at 379,21.5 h3.5
  text "Листов" at 388,21.5 h3.5
  text "1" at 405.5,21.5 h3.5
  text "Н.контр." at 231.5,11.5 h3.5
  text "*" at 250,11.5 h3.5
  text "*" at 389,11 h5
  text "Инв. № подл." at 11.5,9.5 h3.5 r90
  text "Утв." at 231.5,6.5 h3.5
  text "*" at 250,6.5 h3.5
  text "2.106-A3" at 235,1.5 h3.5
  text "Копировал" at 310,1.5 h3.5
  text "Формат А3" at 370,1.5 h3.5
Title Bot 2:
  lines w0.3: 125,10 190,10 ; 125,15 190,15
  lines w0.75: 5,13 15,13 ; 5,20 190,20 190,5 202,5 ; 15,5 15,20 ; 125,5 125,20 ; 135,5 135,20 ; 150,5 150,20 ; 173,5 173,20 ; 183,5 183,20 ; 330,292 330,278 400,278 ; 400,30 412,30 ; 400,65 412,65 ; 400,90 412,90 ; 400,115 412,115 ; 400,150 412,150 412,5 400,5 ; 407,5 407,150 ; 400,5 400,292 5,292 5,5 400,5
  text "Подп. и дата" at 408.161,123 h3.5 r270
  text "Инв. № дубл." at 408.161,94 h3.5 r270
  text "Взам. инв. №" at 408.161,68.5 h3.5 r270
  text "Подп. и дата" at 408.161,37.5 h3.5 r270
  text "Лист" at 13,15 h3.5
  text "Инв. № подл." at 408.161,9.5 h3.5 r270
  text "2" at 11,8 h3.5
  text "Дата" at 133.161,6.5 h3.5
  text "Подп." at 145.661,6.5 h3.5
  text "№ докум." at 167.161,6.5 h3.5
  text "Лист" at 181.161,6.5 h3.5
  text "Изм." at 188.661,6.5 h3.5
  text "Формат А3" at 49.661,1.5 h3.5
  text "Копировал" at 109.661,1.5 h3.5
  text "2.106-A3" at 184.661,1.5 h3.5

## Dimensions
95,167.5 to 95,122.5 on Dimmentions
95,167.5 to 275,167.5 on Dimmentions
